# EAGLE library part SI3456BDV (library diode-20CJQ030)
Vishay Siliconix Si3456BDVY N-Channel 30-V (D-S) MOSFET FEATURES: TrenchFET Power MOSFET 100% Rg Tested Please send any comments to: messi@users.sourceforge.net
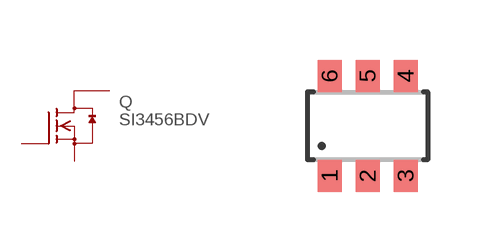
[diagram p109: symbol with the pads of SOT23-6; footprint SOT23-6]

Designator prefix Q

## SI3456BDVSOT-5-6  [SOT23-6]
1  D  pas
2  D  pas
3  G  pas
4  S  pas
5  D  pas
6  D  pas

## Footprint SOT23-6 (pad centres in mm)
Small Outline Transistor 6 lead
smd 0.6 x 0.8: 1 -0.95,-1.25; 2 0,-1.25; 3 0.95,-1.25; 4 0.95,1.25; 5 0,1.25; 6 -0.95,1.25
